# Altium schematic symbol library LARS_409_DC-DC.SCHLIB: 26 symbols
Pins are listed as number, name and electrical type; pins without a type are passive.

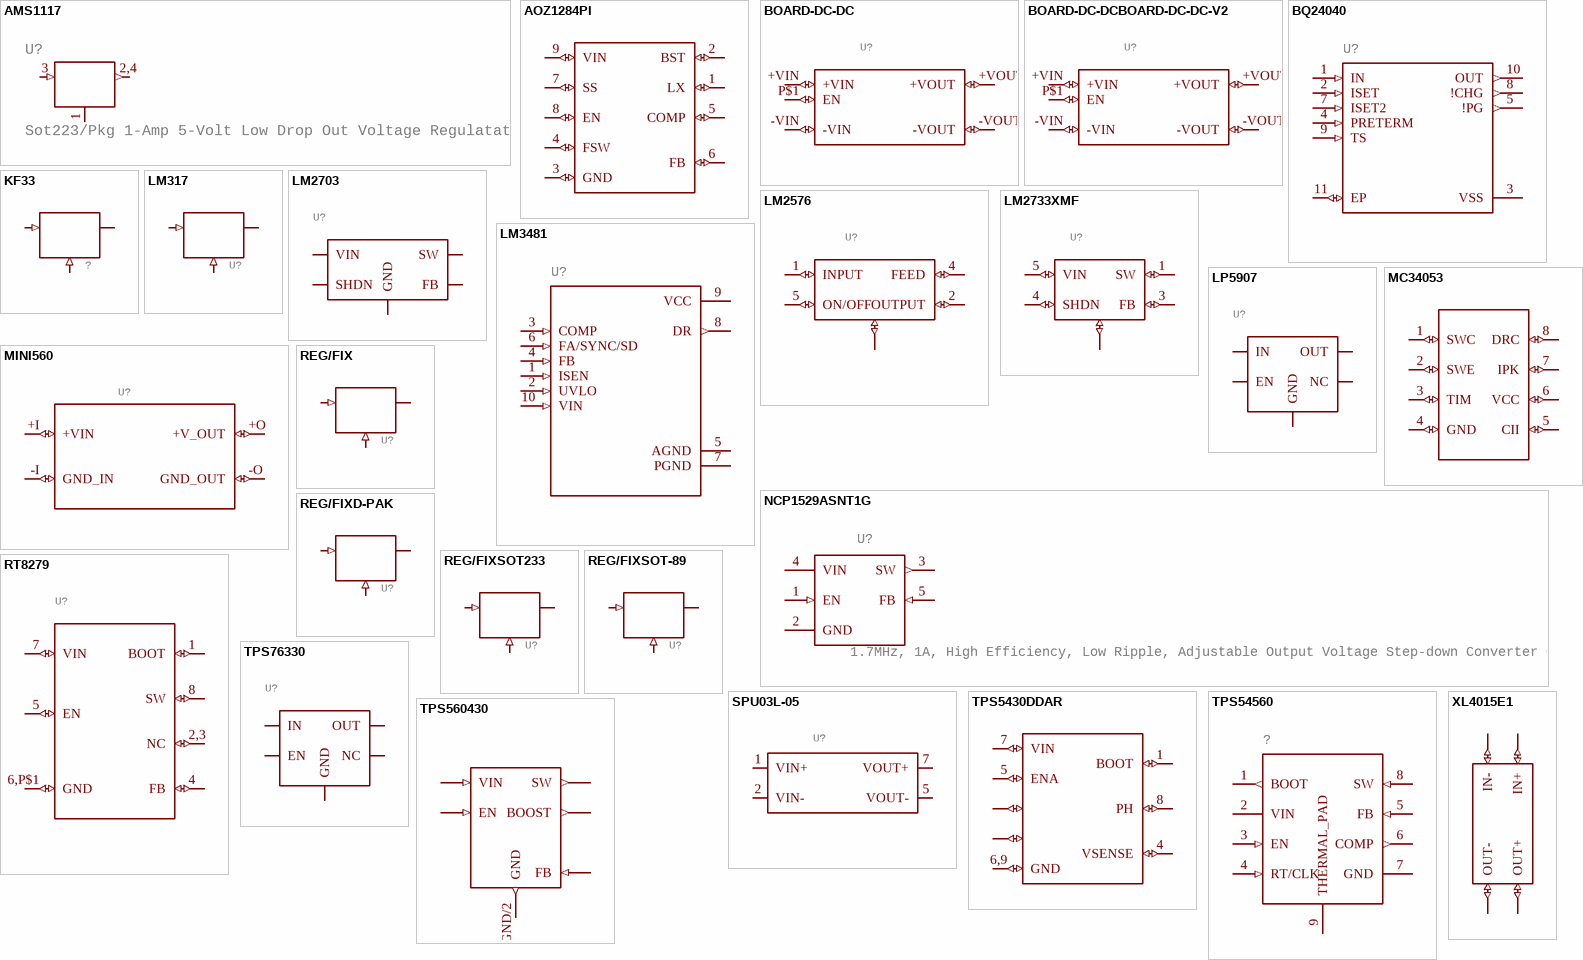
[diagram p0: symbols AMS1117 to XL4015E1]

## AMS1117
designator U?, comment Sot223/Pkg 1-Amp 5-Volt Low Drop Out Voltage Regulatator
GateName_1: G$1; SymbolName_1: AMS1117
footprint SOT233
pins: 1 ADJ/GND (power), 2,4 VOUT (out), 3 VIN (in)

## AOZ1284PI
designator U?
GateName_1: G$1; SymbolName_1: AOZ1284; DeviceSetName: AOZ1284PI
footprint HSOIC(8)
pins: 1 LX (io), 2 BST (io), 3 GND (io), 4 FSW (io), 5 COMP (io), 6 FB (io), 7 SS (io), 8 EN (io), 9 VIN (io)

## BOARD-DC-DC
designator U?
GateName_1: G$1; SymbolName_1: BOARD-DC-DC
footprint BOARD-DC-DC
pins: +VIN (io), +VOUT (io), -VIN (io), -VOUT (io), P$1 EN (io)

## BOARD-DC-DCBOARD-DC-DC-V2
designator U?
GateName_1: G$1; SymbolName_1: BOARD-DC-DC; DeviceName: BOARD-DC-DC-V2
footprint BOARD-DC-DC_V2
pins: +VIN (io), +VOUT (io), -VIN (io), -VOUT (io), P$1 EN (io)

## BQ24040
designator U?
GateName_1: G$1; SymbolName_1: BQ24040
footprint WSON(10)
pins: 1 IN (in), 2 ISET (in), 3 VSS (power), 4 PRETERM (in), 5 !PG (out), 7 ISET2 (in), 8 !CHG (out), 9 TS (in), 10 OUT (out), 11 EP (io)

## KF33
designator ?
GateName_1: G$1; SymbolName_1: REG/FIX; DeviceSetName: KF33
footprint D-PAK
pins: 1 IN (in), 3 OUT, 4 ADJ/GND (in)

## LM317
designator U?
GateName_1: G$1; SymbolName_1: REG/FIX; DeviceSetName: LM317
footprint D-PAK
pins: 1 ADJ/GND (in), 3 IN (in), 4 OUT

## LM2576
designator U?
GateName_1: G$1; SymbolName_1: LM2576
footprint TO-263-5
pins: 1 INPUT (io), 2 OUTPUT (io), 3,6 GND (io), 4 FEED (io), 5 ON/OFF (io)

## LM2703
designator U?
GateName_1: G$1; SymbolName_1: LM2703
footprint SOT-23-5
pins: 1 SW (io), 2 GND (io), 3 FB (io), 4 SHDN (io), 5 VIN (io)

## LM2733XMF
designator U?
GateName_1: G$1; SymbolName_1: LM2733; DeviceSetName: LM2733XMF
footprint SOT-23-5
pins: 1 SW (io), 2 GND (io), 3 FB (io), 4 SHDN (io), 5 VIN (io)

## LM3481
designator U?
GateName_1: G$1; SymbolName_1: LM3481
footprint VSSOP(10)
pins: 1 ISEN (in), 2 UVLO (in), 3 COMP (in), 4 FB (in), 5 AGND (power), 6 FA/SYNC/SD (in), 7 PGND (power), 8 DR (out), 9 VCC (power), 10 VIN (in)

## LP5907
designator U?
GateName_1: G$1; SymbolName_1: TPS76330; DeviceSetName: LP5907
footprint SOT-23-5
pins: 1 IN (io), 2 GND (io), 3 EN (io), 4 NC (io), 5 OUT (io)

## MC34053
designator U?
GateName_1: G$1; SymbolName_1: MC34063; DeviceSetName: MC34053
footprint SOIC127P600X175-8N
pins: 1 SWC (io), 2 SWE (io), 3 TIM (io), 4 GND (io), 5 CII (io), 6 VCC (io), 7 IPK (io), 8 DRC (io)

## MINI560
designator U?
GateName_1: G$1; SymbolName_1: MINI560
footprint MINI560_OTB
pins: +I +VIN (io), +O +V_OUT (io), -I GND_IN (io), -O GND_OUT (io)

## NCP1529ASNT1G
designator U?, comment 1.7MHz, 1A, High Efficiency, Low Ripple, Adjustable Output Voltage Step-down Converter Check prices
GateName_1: A; SymbolName_1: NCP1529ASNT1G
footprint SOT-23-5
pins: 1 EN (in), 2 GND, 3 SW (out), 4 VIN (power), 5 FB (in)

## REG/FIX
designator U?
GateName_1: G$1; SymbolName_1: REG/FIX
footprint SOT23
pins: 1 IN (in), 2 OUT, 3 ADJ/GND (in)

## REG/FIXD-PAK
designator U?
GateName_1: G$1; SymbolName_1: REG/FIX; DeviceName: D-PAK
footprint D-PAK
pins: 1 ADJ/GND (in), 3 IN (in), 4 OUT

## REG/FIXSOT233
designator U?
GateName_1: G$1; SymbolName_1: REG/FIX; DeviceName: SOT233
footprint SOT233
pins: 1 ADJ/GND (in), 2,4 OUT, 3 IN (in)

## REG/FIXSOT-89
designator U?
GateName_1: G$1; SymbolName_1: REG/FIX; DeviceName: SOT-89
footprint SOT-89
pins: 1 OUT, 2 ADJ/GND (in), 3 IN (in)

## RT8279
designator U?
GateName_1: G$1; SymbolName_1: RT8279
footprint SOIC127P599X155-8N
pins: 1 BOOT (io), 2,3 NC (io), 4 FB (io), 5 EN (io), 6,P$1 GND (io), 7 VIN (io), 8 SW (io)

## SPU03L-05
designator U?
GateName_1: G$1; SymbolName_1: SPU03L-05
footprint SPU03L-05
pins: 1 VIN+ (io), 2 VIN- (io), 5 VOUT- (io), 7 VOUT+ (io)

## TPS5430DDAR
designator U?
GateName_1: G$1; SymbolName_1: TPS543X; DeviceSetName: TPS5430DDAR
footprint HSOIC(8)
pins: 1 BOOT (io), 2 NOCONNECT (io), 3 NOCONNECT1 (io), 4 VSENSE (io), 5 ENA (io), 6,9 GND (io), 7 VIN (io), 8 PH (io)

## TPS54560
designator ?
GateName_1: G$1; SymbolName_1: TPS54560B; DeviceSetName: TPS54560
footprint HSOIC(8)
pins: 1 BOOT (out), 2 VIN (power), 3 EN (in), 4 RT/CLK (in), 5 FB (in), 6 COMP (out), 7 GND (power), 8 SW (in), 9 THERMAL_PAD (power)

## TPS76330
designator U?
GateName_1: G$1; SymbolName_1: TPS76330
footprint SOT-23-5
pins: 1 IN (io), 2 GND (io), 3 EN (io), 4 NC (io), 5 OUT (io)

## TPS560430
designator U?
GateName_1: G$1; SymbolName_1: TPS560430
footprint SOT-23-6
pins: BOOST/1 BOOST (out), EN/4 EN (in), FB/3 FB (in), GND/2 GND (out), IN/5 VIN (in), SW/6 SW (out)

## XL4015E1
designator U?
GateName_1: G$1; SymbolName_1: XL4015E1
footprint XL4015E1
pins: IN+ (io), IN- (io), OUT+ (io), OUT- (io)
